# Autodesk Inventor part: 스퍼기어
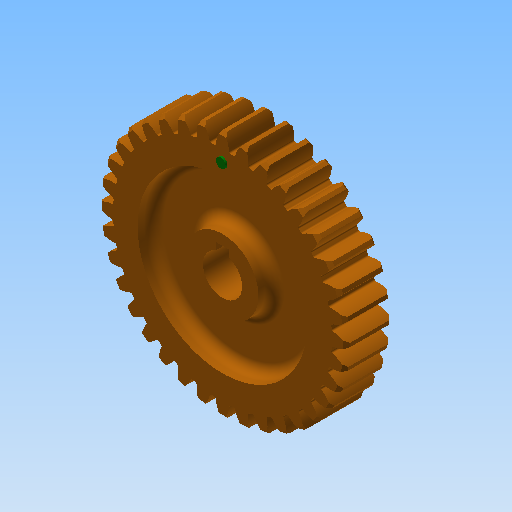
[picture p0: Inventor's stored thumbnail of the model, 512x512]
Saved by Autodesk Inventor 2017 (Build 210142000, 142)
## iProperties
Created: 2019-01
Part Number: 스퍼기어
Material: 알루미늄 6061
Document SubType Name: Modeling
Designer: mduedu
Density: 2.71 g/cm^3
Mass: 108.18 g
Surface Area: 169.519 cm^2
Volume: 39.919 cm^3
Appearance: 주황색
Author: mduedu
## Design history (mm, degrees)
sketch "스케치1"
  geometry: C1 r 33.5 at (0, 0); C2 r 36 at (0, 0); C3 r 38 at (0, 0); 1 further point
  constraints: 3 centre point, 3 coincident
  dimensions: "d0" = 67 diameter of C1; "d2" = 72 diameter of C2; "d3" = 76 diameter of C3
extrude "돌출1" new body sketch "스케치1" distance "d4" = 14; taper "d5" = 0 deg
sketch "스케치2"
  geometry: L1 (0, 0)-(-38, 0); L2 (0, 0)-(0, 38); L3 (-0.57, 0)-(-0.57, 37.996); L4 (-1.57, 0)-(-1.57, 35.966); L5 (-2.07, 0)-(-2.07, 33.436); A1 r 38 centre (0, 0) between (-38, 0) and (0, 38) reference; A2 r 9.246 centre (7.162, 32.926) between (-0.57, 37.996) and (-2.07, 33.436); A3 r 9.246 centre (-7.162, 32.926) between (2.07, 33.436) and (0.57, 37.996); A4 r 33.5 centre (0, 0) between (2.07, 33.436) and (-2.07, 33.436); A5 r 38 centre (0, 0) between (0.57, 37.996) and (-0.57, 37.996); 2 further points
  constraints: 12 point on circle, 10 end point, 4 centre point, 3 parallel, 3 symmetric about line, 2 coincident, 1 horizontal, 1 perpendicular, 5 other
  dimensions: "d6" = 0.5 distance between parallel lines of L4 L5; "d8" = 1 distance between parallel lines of L3 L4; "d9" = 1.57 distance between parallel lines of L2 L4
extrude "돌출2" join sketch "스케치2" stored distance "d10" = 14; taper "d11" = 0 deg
chamfer "모따기1" distance "d12" = 1; stored, may be unused: second distance "d13" = 2, angle "d14" = 45 deg
fillet "모깎기1" dims "d15" = 0.5
sketch "스케치3"
  geometry: C1 r 11 at (0, 0); 1 further point
  constraints: 1 centre point, 1 coincident
  dimensions: "d19" = 22 diameter of C1
extrude "돌출3" join sketch "스케치3" distance "d20" = 7; taper "d21" = 0 deg
sketch "스케치4"
  geometry: C1 r 11 at (0, 0); C2 r 26 at (0, 0); 1 further point
  constraints: 2 centre point, 2 coincident
  dimensions: "d23" = 22 diameter of C1; "d24" = 52 diameter of C2
extrude "돌출4" cut sketch "스케치4" distance "d25" = 5; taper "d26" = 0 deg
fillet "모깎기3" dims "d27" = 3
node "작업 평면1"
sketch "스케치5" dims "d28" = 60
  geometry: C1 r 1.5 at (0, 30); 2 further points
  constraints: 2 vertical alignment, 1 centre point, 1 coincident, 2 other
  dimensions: "d29" = 3 diameter of C1
extrude "돌출5" join sketch "스케치5" distance "d30" = 0.5; taper "d31" = 0 deg
sketch "스케치6"
  geometry: L1 (-2, 5.657)-(2, 5.657); L2 (2, 5.657)-(2, 7.8); L3 (2, 7.8)-(-2, 7.8); L4 (-2, 7.8)-(-2, 5.657); A1 r 6 centre (0, 0) between (-2, 5.657) and (2, 5.657); 1 further point
  constraints: 8 end point, 2 parallel, 2 point on circle, 1 centre point, 1 coincident, 1 horizontal, 1 perpendicular
  dimensions: "d32" = 13.8 dimension on A1 L3; "d34" = 4 distance of L2.end L3.end; "d35" = 12 diameter of A1
extrude "돌출6" cut sketch "스케치6" stored distance "d36" = 0.5; taper "d37" = 0 deg
chamfer "모따기2" distance "d38" = 1; stored, may be unused: second distance "d39" = 2, angle "d40" = 45 deg
node "솔리드1"
pattern_circular "원형 패턴1" dims angle "d17" = 360 deg
mirror "대칭1"
